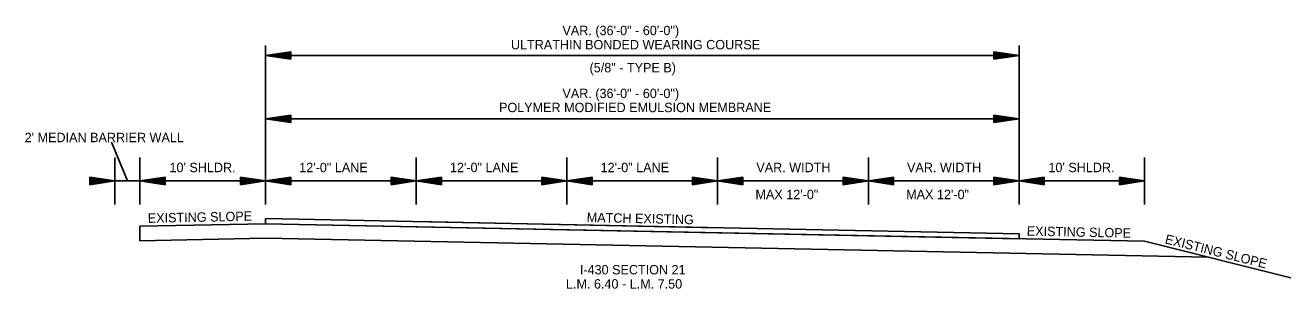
# Model space of a CAD drawing. Extents: x 34757 to 38214, y 51436 to 59430.
# Drawn here: x 37205 to 38213, y 59220 to 59430 of the extents above; entities that cross this region are included whole.
import ezdxf

# ---------------------------------------------------------------- set-up
doc = ezdxf.new("R2010")
doc.units = 0
for name, color, linetype in [('Default', 7, 'Continuous'), ('R_Border', 7, 'Continuous'), ('R_Draft', 7, 'Continuous')]:
    doc.layers.add(name, color=color, linetype=linetype)

msp = doc.modelspace()

# ---------------------------------------------------------------- linework, layer by layer
at = {"layer": 'Default'}
for p, q in [((37396.2, 59286.9), (37396.2, 59413.6)), ((37996.2, 59286.9), (37996.2, 59413.6)), ((37416.2, 59408.5), (37396.2, 59405.5)), ((37996.2, 59405.5), (37396.2, 59405.5)), ((37416.2, 59402.5), (37396.2, 59405.5)), ((37416.2, 59408), (37399.5, 59405.5)), ((37416.2, 59403), (37399.5, 59405.5)), ((37416.2, 59407.5), (37402.9, 59405.5)), ((37416.2, 59403.5), (37402.9, 59405.5)), ((37416.2, 59407), (37406.3, 59405.5)), ((37416.2, 59404), (37406.3, 59405.5)), ((37416.2, 59406.4), (37409.7, 59405.5)), ((37416.2, 59404.5), (37409.7, 59405.5)), ((37416.2, 59405.9), (37413, 59405.5)), ((37416.2, 59405), (37413, 59405.5)), ((37416.2, 59402.5), (37416.2, 59408.5)), ((37976.2, 59408.5), (37996.2, 59405.5)), ((37976.2, 59408.5), (37976.2, 59402.5)), ((37976.2, 59408), (37992.8, 59405.5)), ((37976.2, 59407.5), (37989.4, 59405.5)), ((37976.2, 59407), (37986, 59405.5)), ((37976.2, 59406.4), (37982.7, 59405.5)), ((37976.2, 59405.9), (37979.3, 59405.5)), ((37976.2, 59402.5), (37996.2, 59405.5)), ((37976.2, 59404.5), (37982.7, 59405.5)), ((37976.2, 59403.5), (37989.4, 59405.5)), ((37976.2, 59403), (37992.8, 59405.5)), ((37976.2, 59404), (37986, 59405.5)), ((37976.2, 59405), (37979.3, 59405.5)), ((37416.2, 59358.1), (37396.2, 59355.1)), ((37996.2, 59355.1), (37396.2, 59355.1)), ((37416.2, 59352.1), (37396.2, 59355.1)), ((37416.2, 59357.6), (37399.5, 59355.1)), ((37416.2, 59352.6), (37399.5, 59355.1)), ((37416.2, 59357.1), (37402.9, 59355.1)), ((37416.2, 59353.1), (37402.9, 59355.1)), ((37416.2, 59356.6), (37406.3, 59355.1)), ((37416.2, 59353.6), (37406.3, 59355.1)), ((37416.2, 59356.1), (37409.7, 59355.1)), ((37416.2, 59354.1), (37409.7, 59355.1)), ((37416.2, 59355.6), (37413, 59355.1)), ((37416.2, 59354.6), (37413, 59355.1)), ((37416.2, 59352.1), (37416.2, 59358.1)), ((37976.2, 59358.1), (37996.2, 59355.1)), ((37976.2, 59358.1), (37976.2, 59352.1)), ((37976.2, 59357.6), (37992.8, 59355.1)), ((37976.2, 59357.1), (37989.4, 59355.1)), ((37976.2, 59356.6), (37986, 59355.1)), ((37976.2, 59356.1), (37982.7, 59355.1)), ((37976.2, 59355.6), (37979.3, 59355.1)), ((37976.2, 59352.1), (37996.2, 59355.1)), ((37976.2, 59354.1), (37982.7, 59355.1)), ((37976.2, 59353.1), (37989.4, 59355.1)), ((37976.2, 59352.6), (37992.8, 59355.1)), ((37976.2, 59353.6), (37986, 59355.1)), ((37976.2, 59354.6), (37979.3, 59355.1)), ((37273.5, 59336.5), (37286.2, 59305.6)), ((37276.2, 59286.9), (37276.2, 59324.2)), ((37296.2, 59286.9), (37296.2, 59324.2)), ((37516.2, 59286.9), (37516.2, 59324.2)), ((37636.2, 59286.9), (37636.2, 59324.2)), ((37756.2, 59286.9), (37756.2, 59324.2)), ((37876.2, 59286.9), (37876.2, 59324.2)), ((38096.2, 59286.9), (38096.2, 59324.2)), ((37256.2, 59308.6), (37276.2, 59305.6)), ((37256.2, 59302.6), (37256.2, 59308.6)), ((37316.2, 59308.6), (37296.2, 59305.6)), ((37316.2, 59308.6), (37316.2, 59302.6)), ((37376.2, 59308.6), (37396.2, 59305.6)), ((37376.2, 59302.6), (37376.2, 59308.6)), ((37416.2, 59308.6), (37396.2, 59305.6)), ((37416.2, 59302.6), (37416.2, 59308.6)), ((37496.2, 59308.6), (37516.2, 59305.6)), ((37496.2, 59308.6), (37496.2, 59302.6)), ((37536.2, 59308.6), (37516.2, 59305.6)), ((37536.2, 59302.6), (37536.2, 59308.6)), ((37616.2, 59308.6), (37636.2, 59305.6)), ((37616.2, 59308.6), (37616.2, 59302.6)), ((37656.2, 59308.6), (37636.2, 59305.6)), ((37656.2, 59302.6), (37656.2, 59308.6)), ((37736.2, 59308.6), (37756.2, 59305.6)), ((37736.2, 59308.6), (37736.2, 59302.6)), ((37776.2, 59308.6), (37756.2, 59305.6)), ((37776.2, 59302.6), (37776.2, 59308.6)), ((37856.2, 59308.6), (37876.2, 59305.6)), ((37856.2, 59308.6), (37856.2, 59302.6)), ((37896.2, 59308.6), (37876.2, 59305.6)), ((37896.2, 59302.6), (37896.2, 59308.6)), ((37976.2, 59308.6), (37996.2, 59305.6)), ((37976.2, 59308.6), (37976.2, 59302.6)), ((38016.2, 59308.6), (37996.2, 59305.6)), ((38016.2, 59302.6), (38016.2, 59308.6)), ((38076.2, 59308.6), (38096.2, 59305.6)), ((38076.2, 59308.6), (38076.2, 59302.6)), ((37256.2, 59308.1), (37272.8, 59305.6)), ((37256.2, 59307.6), (37269.4, 59305.6)), ((37256.2, 59307.1), (37266, 59305.6)), ((37256.2, 59306.6), (37262.7, 59305.6)), ((37256.2, 59306.1), (37259.3, 59305.6)), ((37256.2, 59302.6), (37276.2, 59305.6)), ((37256.2, 59304.6), (37262.7, 59305.6)), ((37256.2, 59303.6), (37269.4, 59305.6)), ((37256.2, 59303.1), (37272.8, 59305.6)), ((37256.2, 59304.1), (37266, 59305.6)), ((37256.2, 59305.1), (37259.3, 59305.6)), ((37296.2, 59305.6), (37276.2, 59305.6)), ((37296.2, 59305.6), (37396.2, 59305.6)), ((37316.2, 59302.6), (37296.2, 59305.6)), ((37316.2, 59308.1), (37299.5, 59305.6)), ((37316.2, 59303.1), (37299.5, 59305.6)), ((37316.2, 59307.6), (37302.9, 59305.6)), ((37316.2, 59303.6), (37302.9, 59305.6)), ((37316.2, 59307.1), (37306.3, 59305.6)), ((37316.2, 59304.1), (37306.3, 59305.6)), ((37316.2, 59306.6), (37309.7, 59305.6)), ((37316.2, 59304.6), (37309.7, 59305.6)), ((37316.2, 59306.1), (37313, 59305.6)), ((37316.2, 59305.1), (37313, 59305.6)), ((37376.2, 59308.1), (37392.8, 59305.6)), ((37376.2, 59307.6), (37389.4, 59305.6)), ((37376.2, 59307.1), (37386, 59305.6)), ((37376.2, 59306.6), (37382.7, 59305.6)), ((37376.2, 59306.1), (37379.3, 59305.6)), ((37376.2, 59302.6), (37396.2, 59305.6)), ((37376.2, 59304.6), (37382.7, 59305.6)), ((37376.2, 59303.6), (37389.4, 59305.6)), ((37376.2, 59303.1), (37392.8, 59305.6)), ((37376.2, 59304.1), (37386, 59305.6)), ((37376.2, 59305.1), (37379.3, 59305.6)), ((37416.2, 59302.6), (37396.2, 59305.6)), ((37396.2, 59305.6), (37516.2, 59305.6)), ((37416.2, 59308.1), (37399.5, 59305.6)), ((37416.2, 59303.1), (37399.5, 59305.6)), ((37416.2, 59307.6), (37402.9, 59305.6)), ((37416.2, 59303.6), (37402.9, 59305.6)), ((37416.2, 59307.1), (37406.3, 59305.6)), ((37416.2, 59304.1), (37406.3, 59305.6)), ((37416.2, 59306.6), (37409.7, 59305.6)), ((37416.2, 59304.6), (37409.7, 59305.6)), ((37416.2, 59306.1), (37413, 59305.6)), ((37416.2, 59305.1), (37413, 59305.6)), ((37496.2, 59308.1), (37512.8, 59305.6)), ((37496.2, 59307.6), (37509.4, 59305.6)), ((37496.2, 59307.1), (37506, 59305.6)), ((37496.2, 59306.6), (37502.7, 59305.6)), ((37496.2, 59306.1), (37499.3, 59305.6)), ((37496.2, 59302.6), (37516.2, 59305.6)), ((37496.2, 59304.6), (37502.7, 59305.6)), ((37496.2, 59303.6), (37509.4, 59305.6)), ((37496.2, 59303.1), (37512.8, 59305.6)), ((37496.2, 59304.1), (37506, 59305.6)), ((37496.2, 59305.1), (37499.3, 59305.6)), ((37516.2, 59305.6), (37636.2, 59305.6)), ((37536.2, 59302.6), (37516.2, 59305.6)), ((37536.2, 59308.1), (37519.5, 59305.6)), ((37536.2, 59303.1), (37519.5, 59305.6)), ((37536.2, 59307.6), (37522.9, 59305.6)), ((37536.2, 59303.6), (37522.9, 59305.6)), ((37536.2, 59307.1), (37526.3, 59305.6)), ((37536.2, 59304.1), (37526.3, 59305.6)), ((37536.2, 59306.6), (37529.7, 59305.6)), ((37536.2, 59304.6), (37529.7, 59305.6)), ((37536.2, 59306.1), (37533, 59305.6)), ((37536.2, 59305.1), (37533, 59305.6)), ((37616.2, 59308.1), (37632.8, 59305.6)), ((37616.2, 59307.6), (37629.4, 59305.6)), ((37616.2, 59307.1), (37626, 59305.6)), ((37616.2, 59306.6), (37622.7, 59305.6)), ((37616.2, 59306.1), (37619.3, 59305.6)), ((37616.2, 59302.6), (37636.2, 59305.6)), ((37616.2, 59304.6), (37622.7, 59305.6)), ((37616.2, 59303.6), (37629.4, 59305.6)), ((37616.2, 59303.1), (37632.8, 59305.6)), ((37616.2, 59304.1), (37626, 59305.6)), ((37616.2, 59305.1), (37619.3, 59305.6)), ((37636.2, 59305.6), (37756.2, 59305.6)), ((37656.2, 59302.6), (37636.2, 59305.6)), ((37656.2, 59308.1), (37639.5, 59305.6)), ((37656.2, 59303.1), (37639.5, 59305.6)), ((37656.2, 59307.6), (37642.9, 59305.6)), ((37656.2, 59303.6), (37642.9, 59305.6)), ((37656.2, 59307.1), (37646.3, 59305.6)), ((37656.2, 59304.1), (37646.3, 59305.6)), ((37656.2, 59306.6), (37649.7, 59305.6)), ((37656.2, 59304.6), (37649.7, 59305.6)), ((37656.2, 59306.1), (37653, 59305.6)), ((37656.2, 59305.1), (37653, 59305.6)), ((37736.2, 59308.1), (37752.8, 59305.6)), ((37736.2, 59307.6), (37749.4, 59305.6)), ((37736.2, 59307.1), (37746, 59305.6)), ((37736.2, 59306.6), (37742.7, 59305.6)), ((37736.2, 59306.1), (37739.3, 59305.6)), ((37736.2, 59302.6), (37756.2, 59305.6)), ((37736.2, 59304.6), (37742.7, 59305.6)), ((37736.2, 59303.6), (37749.4, 59305.6)), ((37736.2, 59303.1), (37752.8, 59305.6)), ((37736.2, 59304.1), (37746, 59305.6)), ((37736.2, 59305.1), (37739.3, 59305.6)), ((37776.2, 59302.6), (37756.2, 59305.6)), ((37756.2, 59305.6), (37876.2, 59305.6)), ((37776.2, 59308.1), (37759.5, 59305.6)), ((37776.2, 59303.1), (37759.5, 59305.6)), ((37776.2, 59307.6), (37762.9, 59305.6)), ((37776.2, 59303.6), (37762.9, 59305.6)), ((37776.2, 59307.1), (37766.3, 59305.6)), ((37776.2, 59304.1), (37766.3, 59305.6)), ((37776.2, 59306.6), (37769.7, 59305.6)), ((37776.2, 59304.6), (37769.7, 59305.6)), ((37776.2, 59306.1), (37773, 59305.6)), ((37776.2, 59305.1), (37773, 59305.6)), ((37856.2, 59308.1), (37872.8, 59305.6)), ((37856.2, 59307.6), (37869.4, 59305.6)), ((37856.2, 59307.1), (37866, 59305.6)), ((37856.2, 59306.6), (37862.7, 59305.6)), ((37856.2, 59306.1), (37859.3, 59305.6)), ((37856.2, 59302.6), (37876.2, 59305.6)), ((37856.2, 59304.6), (37862.7, 59305.6)), ((37856.2, 59303.6), (37869.4, 59305.6)), ((37856.2, 59303.1), (37872.8, 59305.6)), ((37856.2, 59304.1), (37866, 59305.6)), ((37856.2, 59305.1), (37859.3, 59305.6)), ((37896.2, 59302.6), (37876.2, 59305.6)), ((37876.2, 59305.6), (37996.2, 59305.6)), ((37896.2, 59308.1), (37879.5, 59305.6)), ((37896.2, 59303.1), (37879.5, 59305.6)), ((37896.2, 59307.6), (37882.9, 59305.6)), ((37896.2, 59303.6), (37882.9, 59305.6)), ((37896.2, 59307.1), (37886.3, 59305.6)), ((37896.2, 59304.1), (37886.3, 59305.6)), ((37896.2, 59306.6), (37889.7, 59305.6)), ((37896.2, 59304.6), (37889.7, 59305.6)), ((37896.2, 59306.1), (37893, 59305.6)), ((37896.2, 59305.1), (37893, 59305.6)), ((37976.2, 59308.1), (37992.8, 59305.6)), ((37976.2, 59307.6), (37989.4, 59305.6)), ((37976.2, 59307.1), (37986, 59305.6)), ((37976.2, 59306.6), (37982.7, 59305.6)), ((37976.2, 59306.1), (37979.3, 59305.6)), ((37976.2, 59302.6), (37996.2, 59305.6)), ((37976.2, 59304.6), (37982.7, 59305.6)), ((37976.2, 59303.6), (37989.4, 59305.6)), ((37976.2, 59303.1), (37992.8, 59305.6)), ((37976.2, 59304.1), (37986, 59305.6)), ((37976.2, 59305.1), (37979.3, 59305.6)), ((38096.2, 59305.6), (37996.2, 59305.6)), ((38016.2, 59302.6), (37996.2, 59305.6)), ((38016.2, 59308.1), (37999.5, 59305.6)), ((38016.2, 59303.1), (37999.5, 59305.6)), ((38016.2, 59307.6), (38002.9, 59305.6)), ((38016.2, 59303.6), (38002.9, 59305.6)), ((38016.2, 59307.1), (38006.3, 59305.6)), ((38016.2, 59304.1), (38006.3, 59305.6)), ((38016.2, 59306.6), (38009.7, 59305.6)), ((38016.2, 59304.6), (38009.7, 59305.6)), ((38016.2, 59306.1), (38013, 59305.6)), ((38016.2, 59305.1), (38013, 59305.6)), ((38076.2, 59308.1), (38092.8, 59305.6)), ((38076.2, 59307.6), (38089.4, 59305.6)), ((38076.2, 59307.1), (38086, 59305.6)), ((38076.2, 59306.6), (38082.7, 59305.6)), ((38076.2, 59306.1), (38079.3, 59305.6)), ((38076.2, 59302.6), (38096.2, 59305.6)), ((38076.2, 59304.6), (38082.7, 59305.6)), ((38076.2, 59303.6), (38089.4, 59305.6)), ((38076.2, 59303.1), (38092.8, 59305.6)), ((38076.2, 59304.1), (38086, 59305.6)), ((38076.2, 59305.1), (38079.3, 59305.6)), ((37296.2, 59269.6), (37296.2, 59258)), ((37516.2, 59273.2), (37756.2, 59268.4)), ((37396.2, 59260), (37296.2, 59258)), ((37396.2, 59260), (38146.8, 59244.9)), ((38096.1, 59257.6), (38212.5, 59228.5))]:
    msp.add_line(p, q, dxfattribs=at)
for points in [[(37396.2, 59271.6), (37296.2, 59269.6)], [(37396.2, 59271.6), (38096, 59257.6)]]:
    msp.add_lwpolyline(points, dxfattribs=at)
msp.add_lwpolyline([(37396.2, 59271.6), (37996.2, 59259.6), (37996.2, 59263.6), (37396.2, 59275.6)], close=True, dxfattribs=at)
at = {"layer": 'R_Draft'}
msp.add_line((37996.2, 59263.6), (37996.2, 59259.6), dxfattribs=at)

# ---------------------------------------------------------------- texts
at = {"layer": 'Default'}
for s, p in [('VAR. (36\'-0" - 60\'-0")', (37632.6, 59421.7)), ('ULTRATHIN BONDED WEARING COURSE', (37591.6, 59410.4)), ('(5/8" - TYPE B)', (37654.2, 59392.1)), ('VAR. (36\'-0" - 60\'-0")', (37632.6, 59371.6)), ('POLYMER MODIFIED EMULSION MEMBRANE', (37582.1, 59360.4)), ("2' MEDIAN BARRIER WALL", (37204.4, 59336.5)), ("10' SHLDR.", (37319.7, 59312.6)), ('12\'-0" LANE', (37423, 59312.6)), ('12\'-0" LANE', (37543, 59312.6)), ('12\'-0" LANE', (37663, 59312.6)), ('VAR. WIDTH', (37787, 59312.6)), ('VAR. WIDTH', (37907, 59312.6)), ("10' SHLDR.", (38019.6, 59312.6)), ('MAX 12\'-0"', (37786.3, 59291.1)), ('MAX 12\'-0"', (37906.3, 59291.1))]:
    msp.add_text(s, height=7.5, dxfattribs=at).set_placement(p)
for s, rotation, p in [('EXISTING SLOPE', 1.2244, (37302.5, 59272.2)), ('MATCH EXISTING', 358.7756, (37651.9, 59272.9)), ('EXISTING SLOPE', 358.7756, (38002.3, 59262.1)), ('EXISTING SLOPE', 345.9632, (38111.9, 59256))]:
    msp.add_text(s, height=7.5, rotation=rotation, dxfattribs=at).set_placement(p)
at = {"layer": 'R_Border'}
for s, p in [('I-430 SECTION 21', (37646.5, 59231.2)), ('L.M. 6.40 - L.M. 7.50', (37635.4, 59219.9))]:
    msp.add_text(s, height=7.5, dxfattribs=at).set_placement(p)

doc.saveas('drawing.dxf')
